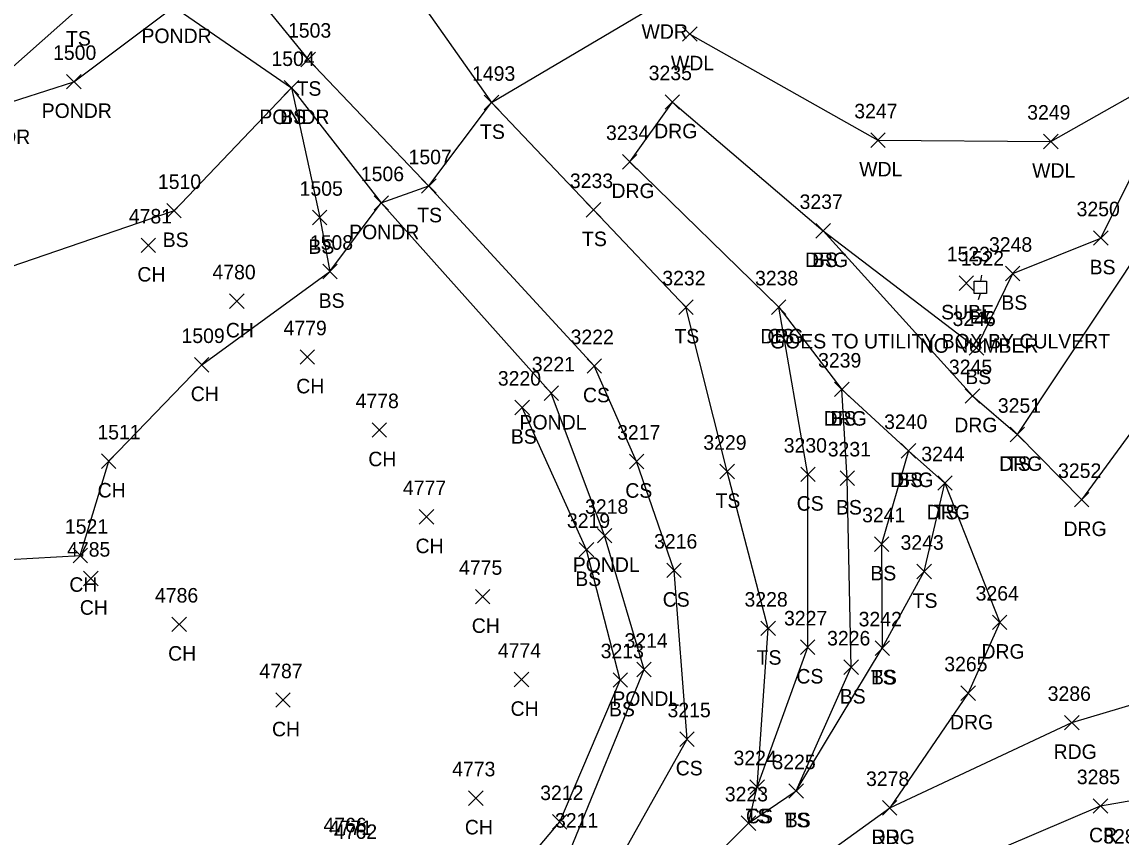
# Model space of a CAD drawing. Extents: x 49137 to 50946, y 9590 to 10709.
# Drawn here: x 50177.5 to 50328.9, y 9799.7 to 9912 of the extents above; entities that cross this region are included whole.
import ezdxf

# ---------------------------------------------------------------- set-up
doc = ezdxf.new("R2010")
doc.units = 0
for name, color, linetype in [('L_A', 7, 'Continuous'), ('L_I', 7, 'Continuous'), ('L_TIC', 7, 'Continuous'), ('LAWA', 7, 'Continuous'), ('LAWE', 7, 'Continuous'), ('LELB', 7, 'Continuous'), ('LSOGP', 7, 'Continuous'), ('P_A', 7, 'Continuous'), ('P_I', 7, 'Continuous'), ('P_TIC', 7, 'Continuous'), ('PEU', 7, 'Continuous'), ('PRC', 7, 'Continuous'), ('R_A', 7, 'Continuous'), ('R_I', 7, 'Continuous'), ('R_TIC', 7, 'Continuous'), ('RDG', 7, 'Continuous'), ('U_A', 7, 'Continuous'), ('U_C', 7, 'Continuous'), ('U_I', 7, 'Continuous'), ('U_TIC', 7, 'Continuous'), ('UEPT', 7, 'Continuous')]:
    doc.layers.add(name, color=color, linetype=linetype)

msp = doc.modelspace()

# ---------------------------------------------------------------- linework, layer by layer
at = {"layer": 'L_TIC'}
for points in [[(50268.38, 9909.32), (50270.38, 9911.32)], [(50270.38, 9909.32), (50268.38, 9911.32)], [(50215.84, 9905.82), (50217.84, 9907.82)], [(50217.84, 9905.82), (50215.84, 9907.82)], [(50183.59, 9902.76), (50185.59, 9904.76)], [(50185.59, 9902.76), (50183.59, 9904.76)], [(50213.56, 9901.92), (50215.56, 9903.92)], [(50215.56, 9901.92), (50213.56, 9903.92)], [(50213.56, 9901.92), (50215.56, 9903.92)], [(50215.56, 9901.92), (50213.56, 9903.92)], [(50213.56, 9901.92), (50215.56, 9903.92)], [(50215.56, 9901.92), (50213.56, 9903.92)], [(50241.1, 9899.88), (50243.1, 9901.88)], [(50243.1, 9899.88), (50241.1, 9901.88)], [(50294.29, 9894.71), (50296.29, 9896.71)], [(50296.29, 9894.71), (50294.29, 9896.71)], [(50318.1, 9894.53), (50320.1, 9896.53)], [(50320.1, 9894.53), (50318.1, 9896.53)], [(50232.45, 9888.39), (50234.45, 9890.39)], [(50234.45, 9888.39), (50232.45, 9890.39)], [(50225.92, 9886.06), (50227.92, 9888.06)], [(50227.92, 9886.06), (50225.92, 9888.06)], [(50197.38, 9884.99), (50199.38, 9886.99)], [(50199.38, 9884.99), (50197.38, 9886.99)], [(50217.44, 9884.05), (50219.44, 9886.05)], [(50219.44, 9884.05), (50217.44, 9886.05)], [(50255.14, 9885.11), (50257.14, 9887.11)], [(50257.14, 9885.11), (50255.14, 9887.11)], [(50286.76, 9882.23), (50288.76, 9884.23)], [(50288.76, 9882.23), (50286.76, 9884.23)], [(50324.98, 9881.23), (50326.98, 9883.23)], [(50326.98, 9881.23), (50324.98, 9883.23)], [(50193.85, 9880.23), (50195.85, 9882.23)], [(50195.85, 9880.23), (50193.85, 9882.23)], [(50218.85, 9876.61), (50220.85, 9878.61)], [(50220.85, 9876.61), (50218.85, 9878.61)], [(50312.84, 9876.34), (50314.84, 9878.34)], [(50314.84, 9876.34), (50312.84, 9878.34)], [(50206.02, 9872.54), (50208.02, 9874.54)], [(50208.02, 9872.54), (50206.02, 9874.54)], [(50267.86, 9871.71), (50269.86, 9873.71)], [(50269.86, 9871.71), (50267.86, 9873.71)], [(50280.63, 9871.71), (50282.63, 9873.71)], [(50282.63, 9871.71), (50280.63, 9873.71)], [(50307.87, 9866.11), (50309.87, 9868.11)], [(50309.87, 9866.11), (50307.87, 9868.11)], [(50215.73, 9864.84), (50217.73, 9866.84)], [(50217.73, 9864.84), (50215.73, 9866.84)], [(50201.19, 9863.77), (50203.19, 9865.77)], [(50203.19, 9863.77), (50201.19, 9865.77)], [(50255.24, 9863.61), (50257.24, 9865.61)], [(50257.24, 9863.61), (50255.24, 9865.61)], [(50249.32, 9859.86), (50251.32, 9861.86)], [(50251.32, 9859.86), (50249.32, 9861.86)], [(50289.32, 9860.39), (50291.32, 9862.39)], [(50291.32, 9860.39), (50289.32, 9862.39)], [(50245.31, 9857.9), (50247.31, 9859.9)], [(50247.31, 9857.9), (50245.31, 9859.9)], [(50225.64, 9854.8), (50227.64, 9856.8)], [(50227.64, 9854.8), (50225.64, 9856.8)], [(50313.49, 9854.16), (50315.49, 9856.16)], [(50315.49, 9854.16), (50313.49, 9856.16)], [(50298.49, 9851.93), (50300.49, 9853.93)], [(50300.49, 9851.93), (50298.49, 9853.93)], [(50188.39, 9850.5), (50190.39, 9852.5)], [(50190.39, 9850.5), (50188.39, 9852.5)], [(50261.07, 9850.46), (50263.07, 9852.46)], [(50263.07, 9850.46), (50261.07, 9852.46)], [(50273.52, 9849.07), (50275.52, 9851.07)], [(50275.52, 9849.07), (50273.52, 9851.07)], [(50284.66, 9848.68), (50286.66, 9850.68)], [(50286.66, 9848.68), (50284.66, 9850.68)], [(50290.07, 9848.15), (50292.07, 9850.15)], [(50292.07, 9848.15), (50290.07, 9850.15)], [(50303.52, 9847.49), (50305.52, 9849.49)], [(50305.52, 9847.49), (50303.52, 9849.49)], [(50232.15, 9842.83), (50234.15, 9844.83)], [(50234.15, 9842.83), (50232.15, 9844.83)], [(50256.66, 9840.25), (50258.66, 9842.25)], [(50258.66, 9840.25), (50256.66, 9842.25)], [(50294.8, 9839.08), (50296.8, 9841.08)], [(50296.8, 9839.08), (50294.8, 9841.08)], [(50184.48, 9837.51), (50186.48, 9839.51)], [(50186.48, 9837.51), (50184.48, 9839.51)], [(50254.17, 9838.31), (50256.17, 9840.31)], [(50256.17, 9838.31), (50254.17, 9840.31)], [(50185.92, 9834.35), (50187.92, 9836.35)], [(50187.92, 9834.35), (50185.92, 9836.35)], [(50266.22, 9835.46), (50268.22, 9837.46)], [(50268.22, 9835.46), (50266.22, 9837.46)], [(50300.66, 9835.3), (50302.66, 9837.3)], [(50302.66, 9835.3), (50300.66, 9837.3)], [(50239.88, 9831.85), (50241.88, 9833.85)], [(50241.88, 9831.85), (50239.88, 9833.85)], [(50198.08, 9828.03), (50200.08, 9830.03)], [(50200.08, 9828.03), (50198.08, 9830.03)], [(50279.18, 9827.47), (50281.18, 9829.47)], [(50281.18, 9827.47), (50279.18, 9829.47)], [(50284.62, 9824.88), (50286.62, 9826.88)], [(50286.62, 9824.88), (50284.62, 9826.88)], [(50294.89, 9824.75), (50296.89, 9826.75)], [(50296.89, 9824.75), (50294.89, 9826.75)], [(50294.89, 9824.75), (50296.89, 9826.75)], [(50296.89, 9824.75), (50294.89, 9826.75)], [(50290.6, 9822.12), (50292.6, 9824.12)], [(50292.6, 9822.12), (50290.6, 9824.12)], [(50245.22, 9820.43), (50247.22, 9822.43)], [(50247.22, 9820.43), (50245.22, 9822.43)], [(50262.09, 9821.8), (50264.09, 9823.8)], [(50264.09, 9821.8), (50262.09, 9823.8)], [(50258.82, 9820.36), (50260.82, 9822.36)], [(50260.82, 9820.36), (50258.82, 9822.36)], [(50212.38, 9817.61), (50214.38, 9819.61)], [(50214.38, 9817.61), (50212.38, 9819.61)], [(50268.01, 9812.23), (50270.01, 9814.23)], [(50270.01, 9812.23), (50268.01, 9814.23)], [(50277.67, 9805.63), (50279.67, 9807.63)], [(50279.67, 9805.63), (50277.67, 9807.63)], [(50277.67, 9805.63), (50279.67, 9807.63)], [(50279.67, 9805.63), (50277.67, 9807.63)], [(50238.93, 9804.1), (50240.93, 9806.1)], [(50240.93, 9804.1), (50238.93, 9806.1)], [(50283.03, 9805.08), (50285.03, 9807.08)], [(50285.03, 9805.08), (50283.03, 9807.08)], [(50283.03, 9805.08), (50285.03, 9807.08)], [(50285.03, 9805.08), (50283.03, 9807.08)], [(50250.48, 9800.83), (50252.48, 9802.83)], [(50252.48, 9800.83), (50250.48, 9802.83)], [(50276.47, 9800.65), (50278.47, 9802.65)], [(50278.47, 9800.65), (50276.47, 9802.65)], [(50276.47, 9800.65), (50278.47, 9802.65)], [(50278.47, 9800.65), (50276.47, 9802.65)]]:
    msp.add_lwpolyline(points, dxfattribs=at)
at = {"layer": 'LAWA'}
msp.add_lwpolyline([(50269.38, 9910.32), (50295.29, 9895.71), (50319.1, 9895.53), (50337.78, 9906.1), (50359.68, 9924.43), (50374.53, 9947.77)], dxfattribs=at)
at = {"layer": 'LAWE'}
for points in [[(50128.8, 9830.05), (50134.29, 9847.3), (50142.11, 9880.9), (50145.47, 9899.84), (50152.79, 9899.24), (50158.84, 9904.9), (50168.73, 9907.32), (50170.14, 9900.19), (50173.37, 9900.16), (50184.59, 9903.76), (50198.34, 9914.07), (50214.56, 9902.92), (50226.92, 9887.06)], [(50250.32, 9860.86), (50226.92, 9887.06)], [(50126.73, 9813.77), (50124.61, 9796.89), (50111.25, 9777.04), (50110.47, 9750.09), (50103.82, 9729.7), (50104.43, 9724.64), (50098.48, 9698.71), (50117.09, 9681.54), (50135.81, 9695.39), (50163.01, 9717.6), (50180.53, 9734.32), (50190.61, 9745.36), (50201.6, 9744.39), (50218.67, 9763.18), (50226.18, 9771.82), (50238.61, 9779.61), (50252.96, 9798.03), (50263.09, 9822.8), (50257.66, 9841.25), (50250.32, 9860.86)]]:
    msp.add_lwpolyline(points, dxfattribs=at)
at = {"layer": 'LELB'}
for points in [[(50154.36, 9970.3), (50163.69, 9962.94), (50180.6, 9949.5), (50195.14, 9945.74), (50210.23, 9933.85), (50230.67, 9917.13), (50242.1, 9900.88)], [(50151.54, 9966.17), (50159.46, 9958.1), (50157.64, 9954.79), (50157.4, 9946.13), (50160.15, 9939.02), (50167.35, 9930.31), (50171.08, 9921.49), (50172.89, 9902.89), (50185.1, 9913.72), (50189.98, 9922.1), (50206.75, 9919.23), (50216.84, 9906.82), (50233.45, 9889.39)], [(50314.49, 9855.16), (50332.43, 9882.14), (50336.66, 9894.79), (50365.35, 9921.11), (50382.8, 9943.34)], [(50287.76, 9883.23), (50308.87, 9867.11), (50313.84, 9877.34), (50325.98, 9882.23), (50337.78, 9906.1)], [(50214.56, 9902.92), (50198.38, 9885.99), (50172.52, 9877.13), (50170.16, 9863.08), (50166.94, 9855.79), (50158.72, 9854.78), (50154.41, 9860.82), (50150.1, 9845.12), (50149.22, 9831.21)], [(50214.56, 9902.92), (50218.44, 9885.05), (50219.85, 9877.61)], [(50256.14, 9886.11), (50242.1, 9900.88)], [(50256.24, 9864.61), (50233.45, 9889.39)], [(50278.67, 9806.63), (50280.18, 9828.47), (50274.52, 9850.07), (50268.86, 9872.71), (50256.14, 9886.11)], [(50277.47, 9801.65), (50278.67, 9806.63), (50285.62, 9825.88), (50285.66, 9849.68), (50281.63, 9872.71)], [(49989.46, 9641.11), (50017.53, 9654.36), (50065.13, 9666.04), (50092.49, 9669.85), (50112.07, 9676.7), (50119.45, 9680.62), (50138.81, 9692.31), (50165.23, 9714.09), (50183.65, 9732.38), (50193.22, 9733.51), (50224.55, 9761.7), (50242.13, 9777.02), (50256.35, 9790.62), (50269.01, 9813.23), (50267.22, 9836.46), (50262.07, 9851.46), (50256.24, 9864.61)], [(50284.03, 9806.08), (50291.6, 9823.12), (50291.07, 9849.15), (50290.32, 9861.39)], [(50130.08, 9813.38), (50127.49, 9796.45), (50115.24, 9773.32), (50112.63, 9748.12), (50107.86, 9731.67), (50105.33, 9723.23), (50101.67, 9703.92), (50120.36, 9686.99), (50133.96, 9697.22), (50159.53, 9719.77), (50180.67, 9741.2), (50186.56, 9749.96), (50198.54, 9748.57), (50219.91, 9767.49), (50235.59, 9782.92), (50251.48, 9801.83), (50259.82, 9821.36), (50255.17, 9839.31), (50246.31, 9858.9)], [(50299.49, 9852.93), (50295.8, 9840.08), (50295.89, 9825.75)], [(50106.75, 9669.47), (50141.52, 9690.01), (50167.92, 9709.84), (50186.51, 9726.93), (50196.39, 9730.26), (50230.66, 9759.7), (50246.59, 9773.44), (50261.12, 9785.36), (50277.47, 9801.65), (50284.03, 9806.08), (50295.89, 9825.75), (50301.66, 9836.3), (50304.52, 9848.49)]]:
    msp.add_lwpolyline(points, dxfattribs=at)
at = {"layer": 'LSOGP'}
msp.add_lwpolyline([(50172.36, 9837.78), (50185.48, 9838.52), (50189.39, 9851.5), (50202.19, 9864.77), (50219.85, 9877.61), (50226.92, 9887.06), (50233.45, 9889.4), (50242.1, 9900.88), (50265.38, 9914.66), (50319.22, 9934.09), (50349.18, 9962.81), (50381.27, 9975.89), (50394.04, 9971.93), (50398.71, 9968.32), (50400.43, 9966.52), (50406.78, 9963.51), (50419.71, 9962.53), (50427.02, 9958.62), (50466.07, 9973.83), (50480.4, 9980.25), (50492.08, 9978.32), (50501.38, 9976.22)], dxfattribs=at)
at = {"layer": 'P_TIC'}
for points in [[(50320.98, 9814.49), (50322.98, 9816.49)], [(50322.98, 9814.49), (50320.98, 9816.49)], [(50295.91, 9802.77), (50297.91, 9804.77)], [(50297.91, 9802.77), (50295.91, 9804.77)], [(50324.93, 9803.02), (50326.93, 9805.02)], [(50326.93, 9803.02), (50324.93, 9805.02)]]:
    msp.add_lwpolyline(points, dxfattribs=at)
at = {"layer": 'PEU'}
msp.add_lwpolyline([(49941.83, 9610.06), (49990.09, 9639.04), (50024.75, 9652.6), (50065.89, 9663.6), (50106.75, 9669.47), (50143.68, 9687.26), (50173.12, 9705.67), (50199.31, 9725.1), (50238.44, 9758.01), (50268.02, 9782.89), (50296.91, 9803.77), (50321.98, 9815.49), (50335.39, 9819.52), (50365.78, 9821.11), (50382.81, 9823.36), (50421.32, 9824.61), (50445.25, 9815.6), (50461.95, 9809.8), (50483.11, 9806.63), (50497.86, 9807.55), (50514.33, 9805.13), (50518.4, 9805.51), (50536.96, 9801.1)], dxfattribs=at)
at = {"layer": 'PRC'}
msp.add_lwpolyline([(49946.14, 9603.32), (49990.57, 9628.34), (50029.06, 9644.26), (50067.71, 9652.16), (50111.82, 9660.88), (50152.59, 9679.83), (50181.44, 9691.98), (50206.17, 9716.71), (50246.84, 9750.25), (50275.55, 9774.21), (50303.89, 9794.63), (50325.93, 9804.02), (50352.75, 9808.7), (50411.41, 9807.82), (50440.83, 9805.17), (50459.62, 9800.88), (50480.38, 9795.99)], dxfattribs=at)
at = {"layer": 'R_TIC'}
for points in [[(50265.99, 9899.96), (50267.99, 9901.96)], [(50267.99, 9899.96), (50265.99, 9901.96)], [(50260.11, 9891.73), (50262.11, 9893.73)], [(50262.11, 9891.73), (50260.11, 9893.73)], [(50260.11, 9891.73), (50262.11, 9893.73)], [(50262.11, 9891.73), (50260.11, 9893.73)], [(50286.76, 9882.23), (50288.76, 9884.23)], [(50288.76, 9882.23), (50286.76, 9884.23)], [(50280.63, 9871.71), (50282.63, 9873.71)], [(50282.63, 9871.71), (50280.63, 9873.71)], [(50289.32, 9860.39), (50291.32, 9862.39)], [(50291.32, 9860.39), (50289.32, 9862.39)], [(50307.32, 9859.48), (50309.32, 9861.48)], [(50309.32, 9859.48), (50307.32, 9861.48)], [(50313.49, 9854.16), (50315.49, 9856.16)], [(50315.49, 9854.16), (50313.49, 9856.16)], [(50298.49, 9851.93), (50300.49, 9853.93)], [(50300.49, 9851.93), (50298.49, 9853.93)], [(50303.52, 9847.49), (50305.52, 9849.49)], [(50305.52, 9847.49), (50303.52, 9849.49)], [(50322.34, 9845.19), (50324.34, 9847.19)], [(50324.34, 9845.19), (50322.34, 9847.19)], [(50311.05, 9828.3), (50313.05, 9830.3)], [(50313.05, 9828.3), (50311.05, 9830.3)], [(50306.72, 9818.56), (50308.72, 9820.56)], [(50308.72, 9818.56), (50306.72, 9820.56)], [(50295.91, 9802.77), (50297.91, 9804.77)], [(50297.91, 9802.77), (50295.91, 9804.77)]]:
    msp.add_lwpolyline(points, dxfattribs=at)
at = {"layer": 'RDG'}
for points in [[(50261.11, 9892.73), (50266.99, 9900.96), (50287.76, 9883.23), (50308.32, 9860.48), (50314.49, 9855.16), (50323.34, 9846.19), (50341.84, 9871.41), (50375.36, 9916.69), (50389.32, 9936.91)], [(50261.11, 9892.73), (50281.63, 9872.71), (50290.32, 9861.39), (50299.49, 9852.93), (50304.52, 9848.49), (50312.05, 9829.3), (50307.72, 9819.56), (50296.91, 9803.77)]]:
    msp.add_lwpolyline(points, dxfattribs=at)
at = {"layer": 'U_TIC'}
for points in [[(50306.46, 9875.02), (50308.46, 9877.02)], [(50308.46, 9875.02), (50306.46, 9877.02)]]:
    msp.add_lwpolyline(points, dxfattribs=at)
at = {"layer": 'UEPT'}
for p, q in [((50309.56, 9877.1), (50309.39, 9876.27)), ((50308.56, 9874.6), (50308.56, 9876.27)), ((50308.56, 9876.27), (50310.22, 9876.27)), ((50309.39, 9875.43), (50309.39, 9875.43)), ((50310.22, 9876.27), (50310.22, 9874.6)), ((50310.22, 9874.6), (50308.56, 9874.6)), ((50309.14, 9873.77), (50309.39, 9874.6))]:
    msp.add_line(p, q, dxfattribs=at)

# ---------------------------------------------------------------- texts
at = {"layer": 'L_A'}
for s, p in [('TS', (50183.51, 9908.72)), ('PONDR', (50193.9, 9909.07)), ('WDR', (50262.74, 9909.66)), ('WDL', (50266.79, 9905.32)), ('TS', (50215.25, 9901.82)), ('PONDR', (50180.16, 9898.76)), ('PONDR', (50210.13, 9897.92)), ('BS', (50213, 9897.92)), ('BS', (50213, 9897.92)), ('PONDR', (50168.93, 9895.16)), ('TS', (50240.51, 9895.88)), ('WDL', (50292.71, 9890.71)), ('WDL', (50316.52, 9890.53)), ('TS', (50231.86, 9884.39)), ('BS', (50196.82, 9880.99)), ('PONDR', (50222.49, 9882.06)), ('TS', (50254.55, 9881.11)), ('BS', (50216.88, 9880.05)), ('BS', (50286.2, 9878.23)), ('BS', (50324.43, 9877.23)), ('CH', (50193.34, 9876.23)), ('BS', (50218.29, 9872.61)), ('BS', (50312.28, 9872.34)), ('CH', (50205.51, 9868.54)), ('TS', (50267.27, 9867.71)), ('CS', (50280.07, 9867.71)), ('BS', (50307.31, 9862.11)), ('CH', (50200.68, 9859.77)), ('CH', (50215.21, 9860.84)), ('CS', (50254.68, 9859.61)), ('PONDL', (50245.95, 9855.86)), ('BS', (50288.76, 9856.39)), ('BS', (50244.75, 9853.9)), ('CH', (50225.13, 9850.8)), ('TS', (50312.9, 9850.16)), ('BS', (50297.93, 9847.93)), ('CH', (50187.87, 9846.5)), ('CS', (50260.51, 9846.46)), ('TS', (50272.93, 9845.07)), ('CS', (50284.11, 9844.68)), ('BS', (50289.51, 9844.15)), ('TS', (50302.93, 9843.49)), ('CH', (50231.63, 9838.83)), ('PONDL', (50253.28, 9836.25)), ('BS', (50253.62, 9834.31)), ('BS', (50294.24, 9835.08)), ('CH', (50183.97, 9833.51)), ('CS', (50265.66, 9831.46)), ('TS', (50300.07, 9831.3)), ('CH', (50185.41, 9830.35)), ('CH', (50239.37, 9827.85)), ('CH', (50197.57, 9824.03)), ('TS', (50278.59, 9823.47)), ('CS', (50284.06, 9820.88)), ('TS', (50294.3, 9820.75)), ('BS', (50294.33, 9820.75)), ('PONDL', (50258.72, 9817.8)), ('BS', (50290.04, 9818.12)), ('CH', (50244.71, 9816.43)), ('BS', (50258.26, 9816.36)), ('CH', (50211.87, 9813.61)), ('CS', (50267.45, 9808.23)), ('TS', (50277.08, 9801.63)), ('CS', (50277.11, 9801.63)), ('TS', (50282.44, 9801.08)), ('BS', (50282.47, 9801.08)), ('CH', (50238.42, 9800.1))]:
    msp.add_text(s, height=2, dxfattribs=at).set_placement(p)
at = {"layer": 'L_I'}
for s, p in [('1503', (50214.07, 9909.82)), ('1500', (50181.73, 9906.76)), ('1504', (50211.79, 9905.92)), ('1504', (50211.79, 9905.92)), ('1504', (50211.79, 9905.92)), ('1493', (50239.41, 9903.88)), ('3247', (50292.03, 9898.71)), ('3249', (50315.84, 9898.53)), ('1507', (50230.67, 9892.39)), ('1506', (50224.1, 9890.06)), ('1510', (50196.16, 9888.99)), ('3233', (50252.88, 9889.11)), ('1505', (50215.67, 9888.05)), ('3237', (50284.5, 9886.23)), ('4781', (50192.16, 9884.23)), ('3250', (50322.64, 9885.23)), ('1508', (50217.08, 9880.61)), ('3248', (50310.58, 9880.34)), ('4780', (50203.67, 9876.54)), ('3232', (50265.6, 9875.71)), ('3238', (50278.37, 9875.71)), ('3246', (50305.56, 9870.11)), ('1509', (50199.41, 9867.77)), ('4779', (50213.46, 9868.84)), ('3222', (50252.98, 9867.61)), ('3239', (50287.05, 9864.39)), ('3221', (50247.63, 9863.86)), ('3220', (50242.96, 9861.9)), ('4778', (50223.38, 9858.8)), ('3251', (50311.8, 9858.16)), ('3240', (50296.14, 9855.93)), ('1511', (50187.83, 9854.5)), ('3217', (50259.38, 9854.46)), ('3229', (50271.25, 9853.07)), ('3230', (50282.32, 9852.68)), ('3231', (50288.38, 9852.15)), ('3244', (50301.26, 9851.49)), ('4777', (50229.89, 9846.83)), ('3218', (50254.97, 9844.25)), ('3219', (50252.47, 9842.31)), ('3241', (50293.11, 9843.08)), ('1521', (50183.36, 9841.51)), ('3216', (50264.47, 9839.46)), ('3243', (50298.4, 9839.3)), ('4785', (50183.66, 9838.35)), ('4775', (50237.62, 9835.85)), ('4786', (50195.76, 9832.03)), ('3228', (50276.92, 9831.47)), ('3227', (50282.36, 9828.88)), ('3242', (50292.63, 9828.75)), ('3242', (50292.63, 9828.75)), ('3214', (50260.4, 9825.8)), ('3226', (50288.29, 9826.12)), ('4774', (50242.96, 9824.43)), ('3213', (50257.12, 9824.36)), ('4787', (50210.13, 9821.61)), ('3215', (50266.32, 9816.23)), ('3224', (50275.41, 9809.63)), ('3224', (50275.41, 9809.63)), ('3225', (50280.77, 9809.08)), ('3225', (50280.77, 9809.08)), ('4773', (50236.67, 9808.1)), ('3212', (50248.79, 9804.83)), ('3223', (50274.21, 9804.65)), ('3223', (50274.21, 9804.65)), ('3211', (50250.83, 9801.03)), ('4766', (50218.95, 9800.39)), ('4771', (50219.7, 9800.01)), ('4771', (50219.7, 9800.01)), ('4762', (50220.39, 9799.48))]:
    msp.add_text(s, height=2, dxfattribs=at).set_placement(p)
at = {"layer": 'P_A'}
for s, p in [('RDG', (50319.47, 9810.49)), ('RDG', (50294.4, 9798.77)), ('CR', (50324.36, 9799.02))]:
    msp.add_text(s, height=2, dxfattribs=at).set_placement(p)
at = {"layer": 'P_I'}
for s, p in [('3286', (50318.66, 9818.49)), ('3278', (50293.65, 9806.77)), ('3285', (50322.67, 9807.02)), ('3284', (50326.3, 9798.84))]:
    msp.add_text(s, height=2, dxfattribs=at).set_placement(p)
at = {"layer": 'R_A'}
for p in [(50264.48, 9895.96), (50258.6, 9887.73), (50258.6, 9887.73), (50285.25, 9878.23), (50279.11, 9867.71), (50287.81, 9856.39), (50305.8, 9855.48), (50311.98, 9850.16), (50296.98, 9847.93), (50302.01, 9843.49), (50320.83, 9841.19), (50309.54, 9824.3), (50305.21, 9814.56), (50294.4, 9798.77)]:
    msp.add_text('DRG', height=2, dxfattribs=at).set_placement(p)
at = {"layer": 'R_I'}
for s, p in [('3235', (50263.73, 9903.96)), ('3234', (50257.85, 9895.73)), ('3234', (50257.85, 9895.73)), ('3237', (50284.5, 9886.23)), ('3238', (50278.37, 9875.71)), ('3239', (50287.05, 9864.39)), ('3245', (50305.06, 9863.48)), ('3251', (50311.8, 9858.16)), ('3240', (50296.14, 9855.93)), ('3244', (50301.26, 9851.49)), ('3252', (50320.09, 9849.19)), ('3264', (50308.74, 9832.3)), ('3265', (50304.42, 9822.56)), ('3278', (50293.65, 9806.77))]:
    msp.add_text(s, height=2, dxfattribs=at).set_placement(p)
at = {"layer": 'U_A'}
for s, p in [('SUBE', (50303.99, 9871.02)), ('EL', (50307.92, 9870.43))]:
    msp.add_text(s, height=2, dxfattribs=at).set_placement(p)
at = {"layer": 'U_C'}
for s, p in [('GOES TO UTILITY BOX BY CULVERT', (50280.44, 9867.02)), ('NO NUMBER', (50301.05, 9866.43))]:
    msp.add_text(s, height=2, dxfattribs=at).set_placement(p)
at = {"layer": 'U_I'}
for s, p in [('1523', (50304.76, 9879.02)), ('1522', (50306.7, 9878.43))]:
    msp.add_text(s, height=2, dxfattribs=at).set_placement(p)

doc.saveas('drawing.dxf')
